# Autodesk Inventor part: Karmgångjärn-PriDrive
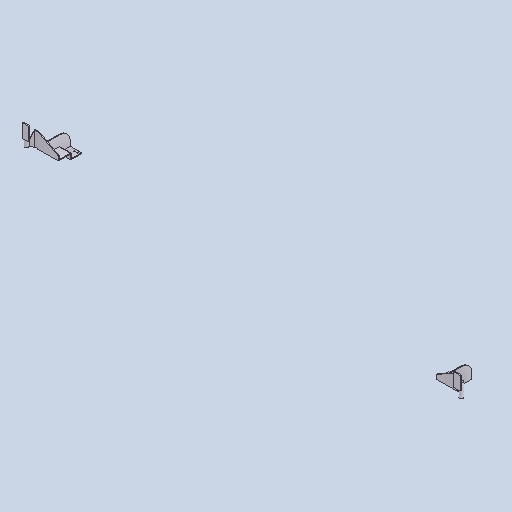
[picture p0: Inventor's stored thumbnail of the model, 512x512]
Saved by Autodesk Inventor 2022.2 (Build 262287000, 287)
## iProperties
Created: 2019-06
Part Number: Karmgångjärn-PriDrive
Material: Aluminum 6061, Welded
Document SubType Name: Modeling
Designer: cl
Density: 2.7 g/cm^3
Appearance: Weld - Aluminum
Author: cl
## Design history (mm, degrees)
sketch "Sketch1"
  geometry: L1 (0, 8)-(225, 8); L2 (228.071, 0)-(0, 0); L3 (0, 0)-(0, 8); L4 (225, 8)-(252.016, 32.325); L5 (225, 8)-(236.561, 8); L6 (228.071, 0)-(257.369, 26.38); L7 (252.016, 32.325)-(257.369, 26.38); C1 r 17.5 at (270, 40); 2 further points
  constraints: 14 end point, 2 coincident, 2 horizontal, 2 parallel, 1 centre point, 1 vertical
  dimensions: "d0" = 35 diameter of C1; "d1" = 40 vertical distance of point (0, 0) C1.centre; "d2" = 270 horizontal distance of point (0, 0) C1.centre; "d3" = 42 deg angle of L5 L4; "d4" = 8 distance between parallel lines of L4 L6; "d5" = 8 distance between parallel lines of L1 L2; "d6" = 225 horizontal distance of point (0, 0) L1.end; "d7" = 1 distance edge to line of C1 L7; "d8" = 90 deg angle of L4 L7; "d10" = 27.76238 distance from line of L5.end L7
extrude "Extrusion1" new body sketch "Sketch1" distance "d11" = 140; taper "d12" = 0 deg
thicken "Thicken1" dims "d13" = 10, "d14" = 80
chamfer "Chamfer1" distance "d15" = 100; stored, may be unused: second distance "d16" = 188.071, angle "d17" = 45 deg
sketch "Sketch2"
  geometry: L1 (-36.354, 140)-(-63.797, 140) reference; L2 (-36.354, 140)-(0, 56); L3 (0, 0)-(0, 140) reference; L4 (0, 140)-(-36.354, 140) reference; L5 (0, 56)-(0, 140); L6 (0, 140)-(-36.354, 140); 1 further point
  constraints: 6 end point, 1 perpendicular, 1 point on line, 1 vertical
  dimensions: "d18" = 56 distance of L3.start L2.end
extrude "Extrusion2" cut sketch "Sketch2" extent not by distance; stored distance "d19" = 29.794; taper "d20" = 0 deg
workplane "Work Plane1"
sketch "Sketch3"
  geometry: L1 (-57.5, 200)-(2.5, 200); L2 (2.5, 200)-(2.5, 70); L3 (2.5, 70)-(-57.5, 70); L4 (-57.5, 70)-(-57.5, 200); L5 (-62.5, 130)-(-27.5, 130) reference; L6 (-27.5, 0)-(-62.5, 0) reference; 1 further point
  constraints: 8 end point, 2 parallel, 1 horizontal, 1 perpendicular
  dimensions: "d22" = 5 distance from line of L5.start L4; "d23" = 60 distance of L1.start L1.end; "d24" = 130 distance of L3.end L1.start; "d25" = 70 distance between parallel lines of L1 L5
extrude "Extrusion3" join sketch "Sketch3" distance "d26" = 10; taper "d27" = 0 deg
sketch "Sketch4"
  geometry: L1 (-225, 8)-(0, 8) reference; L2 (0, 8)-(-198.421, 8); L3 (-115, -91.704)-(-115, -111.704); L4 (-115, -111.704)-(0, -111.704); L5 (0, -111.704)-(0, 8); L6 (-198.421, 8)-(-115, -91.704); 1 further point
  constraints: 10 end point, 2 parallel, 1 horizontal, 1 perpendicular, 1 point on line
  dimensions: "d29" = 115 distance of L3.end L4.end; "d33" = 83.42111 distance from line of L2.end L3; "d62" = 130 distance of L2.end L3.start; "d63" = 20 distance of L3.start L3.end
extrude "Extrusion4" join sketch "Sketch4" stored distance "d35" = 8; taper "d36" = 0 deg
fillet "Fillet1" dims "d37" = 2
sketch "Sketch5"
  geometry: L1 (81.748, 0)-(0, 0) reference; L2 (0, 0)-(-115, 0); L3 (-115, 0)-(-115, -50); L4 (-115, -50)-(0, -50); L5 (0, -50)-(0, 0); L6 (-115, 8)-(-115, 0) reference
  constraints: 8 end point, 2 parallel, 1 collinear, 1 horizontal, 1 perpendicular
  dimensions: "d64" = 50 distance of L3.end L2.end
extrude "Extrusion5" join sketch "Sketch5" distance "d39" = 8; taper "d40" = 0 deg
sketch "Sketch6"
  geometry: L1 (115, -247.408)-(0, -247.408) reference; L2 (0, -247.408)-(115, -247.408); L3 (115, -247.408)-(115, -342.408); L4 (115, -342.408)-(0, -342.408); L5 (0, -342.408)-(0, -247.408); L6 (115, -239.408)-(115, -247.408) reference; 2 further points
  constraints: 8 end point, 2 parallel, 1 collinear, 1 horizontal, 1 perpendicular
  dimensions: "d65" = 95 distance of L2.end L3.end
extrude "Extrusion6" join sketch "Sketch6" distance "d42" = 8; taper "d43" = 0 deg
fillet "Fillet2" dims "d44" = 4
sketch "Sketch7"
  geometry: L1 (-91.704, -8)-(-91.704, -105.147) reference; L2 (-91.704, -105.147)-(-99.704, -105.147) reference; L3 (-99.704, -105.147)-(-99.704, -2) reference; L4 (-97.704, 0)-(0, 0) reference; L5 (0, 0)-(20, 0) reference; L6 (20, 0)-(20, -4) reference; L7 (16, -8)-(0, -8) reference; L8 (0, 0)-(0, -8) reference; L9 (0, -8)-(-91.704, -8) reference; L10 (20, 0)-(20, 50) reference; L11 (20, 50)-(123, 50) reference; L12 (28, 42)-(28, 0) reference; L13 (28, 0)-(20, 0) reference; L14 (123, 50)-(123, 42) reference; L15 (123, 42)-(28, 42) reference; L16 (-91.704, -4)-(-91.704, -144) reference; L17 (-91.704, -103)-(123, -103); L18 (28, 42)-(123, 42) reference; L19 (123, -103)-(123, 42); A1 r 2 centre (-97.704, -2) between (-97.704, 0) and (-99.704, -2) reference; A2 r 4 centre (16, -4) between (16, -8) and (20, -4) reference; 1 further point
  constraints: 4 end point, 1 horizontal, 1 perpendicular, 1 point on line
  dimensions: "d66" = 145 distance of L17.end L14.end
extrude "Extrusion7" join sketch "Sketch7" distance "d46" = 8; taper "d47" = 0 deg
fillet "Fillet3" dims "d48" = 100
sketch "Sketch8"
  geometry: L1 (0, -342.408)-(115, -342.408) reference; L2 (115, -239.408)-(115, -342.408) reference; 3 further points
  dimensions: "d68" = 20 distance from line of L1 point (95, -322.408); "d69" = 0 vertical distance of point (95, -322.408) point (70, -322.408); "d70" = 25 distance of point (95, -322.408) point (70, -322.408); "d71" = 20 distance from line of L2 point (95, -322.408); "d72" = 40 horizontal distance of point (30, -287.408) point (70, -322.408); "d73" = 35 vertical distance of point (70, -322.408) point (30, -287.408)
hole "Hole1" sketch "Sketch8" at (30, -287.408), (70, -322.408), (95, -322.408) diameter "d55" = 12; stored, may be unused: countersink angle "d59" = 90 deg, drill point angle "d61" = 118 deg; dims "d56" = 6, "d57" = 4, "d58" = 2, "d60" = 8
workplane "Work Plane2"
mirror "Mirror1"
body "Solid1"
node "Projected Loop1"
node "Project Cut Edges1"
other parameters: "d21" = 57, "BladBredd" = 1333.33333, "Fönsterhöjd" = 862, "d74" = 2025.01 (computed from DagBredd)
